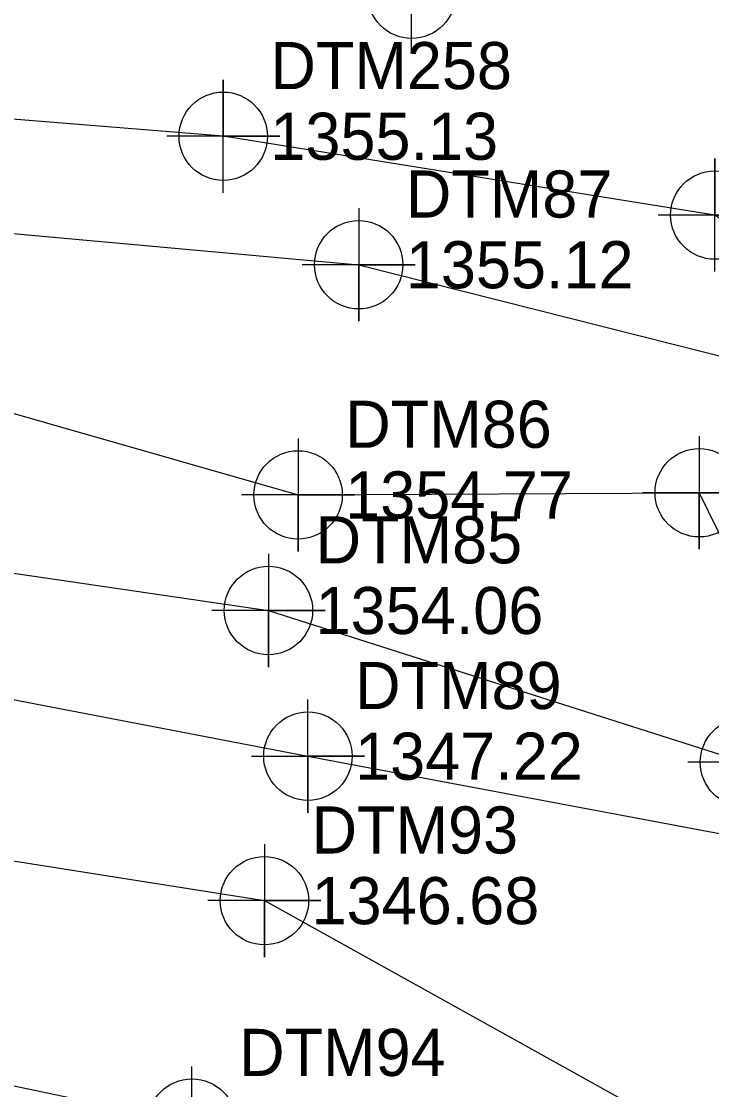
# Model space of a CAD drawing. Extents: x 1251905 to 1252853, y 859795 to 860170.
# Drawn here: x 1251978.6 to 1252015.3, y 860028.5 to 860085.2 of the extents above; entities that cross this region are included whole.
import ezdxf

# ---------------------------------------------------------------- set-up
doc = ezdxf.new("R2010")
doc.units = 0
for name, color, linetype in [('Exist DTM Breakline', 7, 'Continuous'), ('Exist DTM Breakline Cogo Elevation', 7, 'Continuous'), ('Exist DTM Breakline Cogo Number', 7, 'Continuous'), ('Exist DTM Breakline Cogo Point CELL', 7, 'Continuous'), ('Exist DTM Breakline Underwater', 7, 'Continuous'), ('Exist DTM Breakline Underwater Cogo Elevation', 7, 'Continuous'), ('Exist DTM Breakline Underwater Cogo Number', 7, 'Continuous'), ('Exist DTM Breakline Underwater Cogo Point CELL', 7, 'Continuous'), ('Exist Hydro Stream or Body of Water', 7, 'Continuous'), ('Exist Hydro Stream or Body of Water Cogo Elevation', 7, 'Continuous'), ('Exist Hydro Stream or Body of Water Cogo Number', 7, 'Continuous'), ('Exist Hydro Stream or Body of Water Cogo Point CELL', 7, 'Continuous'), ('Exist Roads Soil', 7, 'Continuous'), ('Exist Roads Soil Cogo Elevation', 7, 'Continuous'), ('Exist Roads Soil Cogo Number', 7, 'Continuous'), ('Exist Roads Soil Cogo Point CELL', 7, 'Continuous')]:
    doc.layers.add(name, color=color, linetype=linetype)

msp = doc.modelspace()

# ---------------------------------------------------------------- linework, layer by layer
at = {"layer": 'Exist DTM Breakline'}
for points in [[(1251930.158, 860079.966), (1251954.171, 860076.105), (1251996.545, 860072.28), (1252018.833, 860066.653), (1252019.501, 860056.104), (1252023.199, 860048.714), (1252025.121, 860048.423)], [(1251929.364, 860075.129), (1251953.388, 860071.501), (1251993.329, 860060.067), (1252014.61, 860060.183), (1252018.569, 860052.108), (1252021.655, 860046.227)], [(1251926.999, 860067.532), (1251948.988, 860060.189), (1251991.758, 860053.937), (1252017.01, 860045.885), (1252022.44, 860046.144), (1252048.657, 860045.032), (1252055.807, 860052.896), (1252053.946, 860054.482), (1252047.904, 860046.493)]]:
    msp.add_lwpolyline(points, dxfattribs=at)
at = {"layer": 'Exist DTM Breakline Cogo Point CELL'}
for points in [[(1251996.545, 860075.28), (1251996.545, 860069.28), (1251996.545, 860072.28), (1251999.545, 860072.28), (1251993.545, 860072.28)], [(1251993.329, 860063.067), (1251993.329, 860057.067), (1251993.329, 860060.067), (1251996.329, 860060.067), (1251990.329, 860060.067)], [(1252014.61, 860063.183), (1252014.61, 860057.183), (1252014.61, 860060.183), (1252017.61, 860060.183), (1252011.61, 860060.183)], [(1251991.758, 860056.937), (1251991.758, 860050.937), (1251991.758, 860053.937), (1251994.758, 860053.937), (1251988.758, 860053.937)], [(1252017.01, 860048.885), (1252017.01, 860042.885), (1252017.01, 860045.885), (1252020.01, 860045.885), (1252014.01, 860045.885)]]:
    msp.add_lwpolyline(points, dxfattribs=at)
for centre in [(1251996.545, 860072.28), (1252014.61, 860060.183), (1251993.329, 860060.067), (1251991.758, 860053.937), (1252017.01, 860045.885)]:
    msp.add_circle(centre, 2.344, dxfattribs=at)
at = {"layer": 'Exist DTM Breakline Underwater'}
msp.add_lwpolyline([(1251927.42, 860049.663), (1251960.607, 860043.428), (1251991.544, 860038.543), (1252023.095, 860021.002), (1252051.108, 860015.006), (1252097.444, 860018.35), (1252136.124, 860025.415), (1252179.795, 860024.836), (1252209.042, 860015.729)], dxfattribs=at)
at = {"layer": 'Exist DTM Breakline Underwater Cogo Point CELL'}
msp.add_lwpolyline([(1251991.544, 860041.543), (1251991.544, 860035.543), (1251991.544, 860038.543), (1251994.544, 860038.543), (1251988.544, 860038.543)], dxfattribs=at)
msp.add_circle((1251991.544, 860038.543), 2.344, dxfattribs=at)
at = {"layer": 'Exist Hydro Stream or Body of Water'}
for points in [[(1251931.145, 860058.535), (1251964.012, 860051.945), (1251993.851, 860046.208), (1252023.877, 860040.562), (1252046.52, 860034.729)], [(1251923.519, 860032.492), (1251957.999, 860032.964), (1251987.699, 860026.743), (1252004.412, 860018.883), (1252004.612, 860014.582), (1251994.716, 860013.049), (1252010.915, 860007.676), (1252019.462, 860003.97), (1252019.665, 860004.195), (1252046.38, 860003.539), (1252090.782, 859996.797), (1252140.715, 860010.791), (1252179.759, 860006.581), (1252205.549, 860000.12)]]:
    msp.add_lwpolyline(points, dxfattribs=at)
at = {"layer": 'Exist Hydro Stream or Body of Water Cogo Point CELL'}
for points in [[(1251990.851, 860046.208), (1251996.851, 860046.208), (1251993.851, 860046.208), (1251993.851, 860043.208), (1251993.851, 860049.208)], [(1251984.699, 860026.743), (1251990.699, 860026.743), (1251987.699, 860026.743), (1251987.699, 860023.743), (1251987.699, 860029.743)]]:
    msp.add_lwpolyline(points, dxfattribs=at)
for centre in [(1251993.851, 860046.208), (1251987.699, 860026.743)]:
    msp.add_circle(centre, 2.344, dxfattribs=at)
at = {"layer": 'Exist Roads Soil'}
msp.add_lwpolyline([(1252027.154, 860067.333), (1252015.44, 860074.915), (1251989.358, 860079.095), (1251956.453, 860081.754)], dxfattribs=at)
at = {"layer": 'Exist Roads Soil Cogo Point CELL'}
for points in [[(1251999.355, 860083.635), (1251999.355, 860089.635), (1251999.355, 860086.635), (1252002.355, 860086.635), (1251996.355, 860086.635)], [(1251989.358, 860076.095), (1251989.358, 860082.095), (1251989.358, 860079.095), (1251992.358, 860079.095), (1251986.358, 860079.095)], [(1252015.44, 860071.915), (1252015.44, 860077.915), (1252015.44, 860074.915), (1252018.44, 860074.915), (1252012.44, 860074.915)]]:
    msp.add_lwpolyline(points, dxfattribs=at)
for centre in [(1251999.355, 860086.635), (1251989.358, 860079.095), (1252015.44, 860074.915)]:
    msp.add_circle(centre, 2.344, dxfattribs=at)

# ---------------------------------------------------------------- texts
at = {"layer": 'Exist DTM Breakline Cogo Elevation'}
for s, p in [('1355.12', (1251999.045, 860071.03)), ('1354.77', (1251995.829, 860058.817)), ('1354.06', (1251994.258, 860052.687))]:
    msp.add_text(s, height=2.5, dxfattribs=at).set_placement(p)
at = {"layer": 'Exist DTM Breakline Cogo Number'}
for s, p in [('DTM87', (1251999.045, 860074.78)), ('DTM86', (1251995.829, 860062.567)), ('DTM85', (1251994.258, 860056.437))]:
    msp.add_text(s, height=2.5, dxfattribs=at).set_placement(p)
at = {"layer": 'Exist DTM Breakline Underwater Cogo Elevation'}
msp.add_text('1346.68', height=2.5, dxfattribs=at).set_placement((1251994.044, 860037.293))
at = {"layer": 'Exist DTM Breakline Underwater Cogo Number'}
msp.add_text('DTM93', height=2.5, dxfattribs=at).set_placement((1251994.044, 860041.043))
at = {"layer": 'Exist Hydro Stream or Body of Water Cogo Elevation'}
msp.add_text('1347.22', height=2.5, dxfattribs=at).set_placement((1251996.351, 860044.958))
at = {"layer": 'Exist Hydro Stream or Body of Water Cogo Number'}
for s, p in [('DTM89', (1251996.351, 860048.708)), ('DTM94', (1251990.199, 860029.243))]:
    msp.add_text(s, height=2.5, dxfattribs=at).set_placement(p)
at = {"layer": 'Exist Roads Soil Cogo Elevation'}
msp.add_text('1355.13', height=2.5, dxfattribs=at).set_placement((1251991.858, 860077.845))
at = {"layer": 'Exist Roads Soil Cogo Number'}
msp.add_text('DTM258', height=2.5, dxfattribs=at).set_placement((1251991.858, 860081.595))

doc.saveas('drawing.dxf')
